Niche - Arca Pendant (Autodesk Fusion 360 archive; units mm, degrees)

design "Arca" references "Arca", "Niche - Chief Architect - Luxe Single Pendant Cordset", "Luxe Single Pendant Cordset - 4ft Standard"
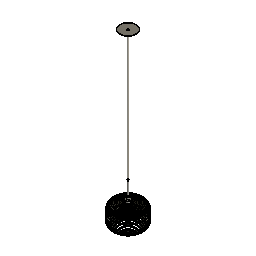
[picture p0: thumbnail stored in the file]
external_derived "ExternalDerived1" bodies "Arca"
external_derived "ExternalDerived2" bodies "Socket Body", "Shade Ring", "Shade Ring +Collar", "Socket", "Body1", "Metal Strain Relief", "Fabric Cord (1)", "Stem (Threaded)"
align "Align1"
external_derived "ExternalDerived3" bodies "G30-Bulb"
align "Align2"
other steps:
derived_base_feature "Derived Base Feature1" bodies "Arca"
derived_base_feature "Derived Base Feature2" bodies "Socket Body", "Shade Ring", "Shade Ring +Collar", "Socket", "Body1", "Metal Strain Relief", "Fabric Cord (1)", "Stem (Threaded)"
derived_base_feature "Derived Base Feature3" bodies "G30-Bulb"
named bodies: "Arca", "Socket Body", "Shade Ring", "Shade Ring +Collar", "Socket", "Body1", "Metal Strain Relief", "Fabric Cord (1)", "Stem (Threaded)", "Cap (Threaded)", "5M Set Screw", "G30-Bulb"

design "Luxe Single Pendant Cordset - 4ft Standard" references "Luxe Canopy - Single Pendant Cordset"
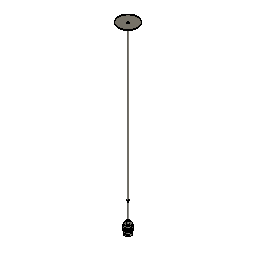
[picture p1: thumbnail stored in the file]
external_derived "ExternalDerived2" bodies "Cap (Threaded)"
move "Move1"
move "Move2"
offset_faces "OffsetFaces1" distance 1051.56
move "Move3"
move "Move4"
move "Move5"
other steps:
derived_base_feature "Derived Base Feature9" bodies "Socket Body", "Shade Ring", "Shade Ring +Collar", "Socket"
derived_base_feature "Derived Base Feature10" bodies "Body1"
derived_base_feature "Derived Base Feature12" bodies "Metal Strain Relief"
derived_base_feature "Derived Base Feature13" bodies "Fabric Cord (1)"
derived_base_feature "Derived Base Feature14" bodies "Stem (Threaded)"
derived_base_feature "Derived Base Feature15" bodies "Cap 9Threaded)", "Cap (Threaded)"
named bodies: "Socket Body", "Shade Ring", "Shade Ring +Collar", "Socket", "Metal Strain Relief", "Fabric Cord (1)", "Stem (Threaded)", "Cap 9Threaded)", "Body1", "Cap (Threaded)", "5M Set Screw"

design "Luxe Canopy - Single Pendant Cordset" references "Luxe Cordset", "Canopy Mounting Bar", "M5 Set Screw", "Canopy Mounting Bar Screw", "Plastic Strain Relief"
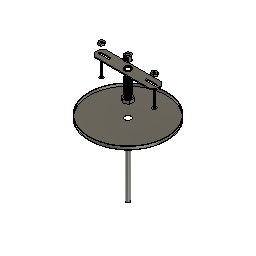
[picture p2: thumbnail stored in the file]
sketch "Sketch1" plane through (0, 0, 0) normal (0, 0, 1) x axis (1, 0, 0)
  circle C1 centre (0, 0) radius 63.5
  point P1 (0, 0)
  point P2 (0, 0)
  coincident P1 P2
  dimension "d1" diameter C1 = 127
extrude "Extrude1" new body sketch "Sketch1" along normal blind 5.08
shell "Shell1" innerThickness 0.762
hole "Hole1" HoleDepth 35.56 HoleDiameter 10.16 TipAngle 118
component_from_bodies "Body->Comp1"
component_insert "Component Insert1"
component_insert "Component Insert2"
component_insert "Component Insert3"
sketch "Sketch2" plane through (0, 0, 0) normal (0, 0, 1) x axis (1, 0, 0)
  circle C1 centre (0, 0) radius 3.175
  point P1 (0, 0)
  point P2 (0, 0)
  coincident P1 P2
  dimension "d8" diameter C1 = 6.35
extrude "Extrude2" new body sketch "Sketch2" along normal blind 127 and against normal blind 127 bodies "Fabric Cord"
component_insert "Component Insert4"
component_insert "Component Insert5"
position "Position1"
sketch "Sketch3" plane through (0, 0, 0.762) normal (0, 0, 1) x axis (-1, 0, 0)
  circle C1 centre (-0.0475, 0.2257) radius 5.08
  circle C2 centre (0, 0) radius 62.738
  circle C3 centre (0, 0) radius 4.826
  concentric C2 C3
  dimension "d13" diameter C3 = 9.652
extrude "Extrude3" new body sketch "Sketch3" profile of C3 along normal blind 25.4 bodies "Threaded Nipple"
shell "Shell2" innerThickness 1.27
thread "Thread1"
sketch "Sketch5" plane through (0, 0, 127) normal (0, 0, 1) x axis (-1, 0, 0)
  line L1 (-6.8191, 3.937) -> (0, 7.874)
  line L2 (-6.8191, -3.937) -> (-6.8191, 3.937)
  line L3 (0, -7.874) -> (-6.8191, -3.937)
  line L4 (6.8191, -3.937) -> (0, -7.874)
  line L5 (6.8191, 3.937) -> (6.8191, -3.937)
  line L6 (0, 7.874) -> (6.8191, 3.937)
  circle C1 centre (0, 0) radius 3.175
  point P2 (0, 0)
  point P9 (0, 0)
  point P3 (0, 7.874)
  coincident P2 P9
  dimension "d20" distance P3 P9 = 7.874
extrude "Extrude4" new body sketch "Sketch5" along normal blind 5.08 bodies "Hex Nut"
move "Move1"
thread "Thread2"
move "Move2" TranslateX 0 TranslateY 0 TranslateZ -55.88
move "Move3" TranslateX 0 TranslateY 0 TranslateZ 60.96
position "Position2"
sketch "Sketch6" plane through (0, 0, 0) normal (0, 0, 1) x axis (1, 0, 0)
  circle C1 centre (0, 0) radius 9.525
  point P1 (0, 0)
  point P2 (0, 0)
  coincident P1 P2
  dimension "d29" diameter C1 = 19.05
extrude "Extrude5" new body sketch "Sketch6" along normal blind 16.129 bodies "Metal Strain Relief"
move "Move4" TranslateX 0 TranslateY 0 TranslateZ -86.36
hole "Hole2" HoleDepth 10.16 HoleDiameter 5.08 TipAngle 118
hole "Hole3" HoleDepth 4.064 HoleDiameter 7.62 TipAngle 180
hole "Hole4" HoleDepth 12.192 HoleDiameter 9.144 TipAngle 180
thread "Thread3" ThreadOffset 0 ThreadLength 6.096
move "Move1" TranslateX 0 TranslateY 0 TranslateZ 68.58
move "Move5" TranslateX 0 TranslateY 0 TranslateZ 138.43
component_insert "Component Insert6"
external_derived "ExternalDerived1" bodies "5M Set Screw"
move "Move6" TranslateX 0 TranslateY 0 TranslateZ -185.42
copy_paste_bodies "CopyPasteBodies1"
move "Move7" TranslateX 0 TranslateY 0 TranslateZ -12.7
offset_faces "OffsetFaces1" distance -152.4
move "Move8"
component_from_bodies "Body->Comp2"
component_from_bodies "Body->Comp3"
component_from_bodies "Body->Comp4"
component_from_bodies "Body->Comp5"
hole "Hole1" HoleDepth 25.4 HoleDiameter 6.35 TipAngle 180
sketch "Sketch7" plane through (0, 0, 0) normal (0, 0, 1) x axis (1, 0, 0)
  line L1 (49.784, 3.9595) -> (52.07, 0)
  line L2 (45.212, 3.9595) -> (49.784, 3.9595)
  line L3 (42.926, 0) -> (45.212, 3.9595)
  line L4 (45.212, -3.9595) -> (42.926, 0)
  line L5 (49.784, -3.9595) -> (45.212, -3.9595)
  line L6 (52.07, 0) -> (49.784, -3.9595)
  point P2 (52.07, 0)
  point P8 (47.498, 0)
  dimension "d63" distance P2 P8 = 4.572
extrude "Extrude6" new body sketch "Sketch7" along normal blind 3.175 bodies "Mounting Hex Nut"
hole "Hole5" HoleDepth 25.4 HoleDiameter 3.81 TipAngle 180
thread "Thread4"
move "Move9"
component_from_bodies "Body->Comp6"
copy_paste "CopyPaste1"
move "Move10"
derived_base_feature "Derived Base Feature3" bodies "Stem (Threaded)", "Cap 9Threaded)"
move "Move11"
component_from_bodies "Body->Comp7"
component_from_bodies "Body->Comp8"
component_from_bodies "Body->Comp9"
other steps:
base_feature "Base Feature1"
base_feature "Base Feature1" bodies "Stem (Threaded)"
base_feature "Base Feature1" bodies "Cap 9Threaded)"
base_feature "Base Feature1" bodies "Fabric Cord"
base_feature "Base Feature1" bodies "Metal Strain Relief"
base_feature "Base Feature1" bodies "Mounting Hex Nut"
base_feature "Base Feature1" bodies "Hex Nut"
base_feature "Base Feature1" bodies "Fabric Cord (1)"
base_feature "Base Feature1" bodies "Threaded Nipple"
derived_base_feature "Derived Base Feature1" bodies "Socket Body", "Shade Ring", "Shade Ring +Collar", "Socket", "Rigid Stem"
derived_base_feature "Derived Base Feature2" bodies "5M Set Screw"
base_feature "Base Feature1" bodies "Fabric Cord", "Fabric Cord (1)"
create_component "CreateComponent1"
remove_body "RemoveBody1"
create_component "CreateComponent2"
remove_body "RemoveBody2"
create_component "CreateComponent3"
remove_body "RemoveBody3"
create_component "CreateComponent4"
remove_body "RemoveBody4"
create_component "CreateComponent5"
remove_body "RemoveBody5"
create_component "CreateComponent6"
remove_body "RemoveBody6"
create_component "CreateComponent7"
remove_body "RemoveBody7"
create_component "CreateComponent8"
remove_body "RemoveBody8"
create_component "CreateComponent9"
remove_body "RemoveBody9"
named bodies: "Fabric Cord", "Threaded Nipple", "Hex Nut", "Metal Strain Relief", "Socket Body", "Shade Ring", "Shade Ring +Collar", "Socket", "Rigid Stem", "5M Set Screw", "Fabric Cord (1)", "Mounting Hex Nut", "Stem (Threaded)", "Cap 9Threaded)"

design "M5 Set Screw"
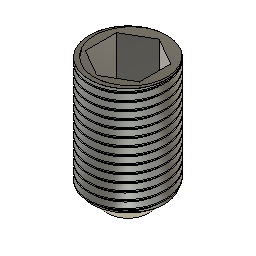
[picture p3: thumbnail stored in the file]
sketch "Sketch1" plane through (0, 0, 0) normal (0, 0, 1) x axis (1, 0, 0)
  circle C1 centre (0, 0) radius 2.5
  point P1 (0, 0)
  point P2 (0, 0)
  coincident P1 P2
  dimension "d1" diameter C1 = 5
extrude "Extrude1" new body sketch "Sketch1" along normal blind 8
sketch "Sketch2" plane through (0, 0, 8) normal (0, 0, 1) x axis (-1, 0, 0)
  line L1 (-1.7321, 1) -> (0, 2)
  line L2 (-1.7321, -1) -> (-1.7321, 1)
  line L3 (0, -2) -> (-1.7321, -1)
  line L4 (1.7321, -1) -> (0, -2)
  line L5 (1.7321, 1) -> (1.7321, -1)
  line L6 (0, 2) -> (1.7321, 1)
  circle C1 centre (0, 0) radius 2.5
  point P2 (0, 0)
  point P9 (0, 0)
  coincident P2 P9
extrude "Extrude2" cut sketch "Sketch2" profile of L1 L2 L3 L4 L5 L6 against normal blind 3
thread "Thread1" ThreadOffset 0.99 ThreadLength 7
chamfer "Chamfer1" distance 1.15

design "Luxe Cordset" references "M5 Set Screw"
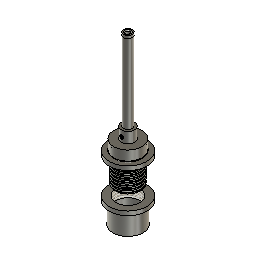
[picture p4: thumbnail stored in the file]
sketch "Sketch1" plane through (0, 0, 0) normal (0, 0, 1) x axis (1, 0, 0)
  circle C1 centre (0, 0) radius 20.6
  point P1 (0, 0)
  point P2 (0, 0)
  coincident P1 P2
  dimension "d11" diameter C1 = 41.2
extrude "Extrude1" new body sketch "Sketch1" along normal blind 14 bodies "Socket Body"
sketch "Sketch2" plane through (0, 0, 14) normal (0, 0, 1) x axis (-1, 0, 0)
  circle C1 centre (0, 0) radius 20.6
  circle C2 centre (0, 0) radius 9.6
  concentric C1 C2
  dimension "d3" diameter C2 = 19.2
extrude "Extrude2" add sketch "Sketch2" profile of C2 along normal blind 15.75
sketch "Sketch3" plane through (0, 0, 29.75) normal (0, 0, 1) x axis (-1, 0, 0)
  circle C1 centre (0, 0) radius 9.6
  circle C2 centre (0, 0) radius 5.75
  concentric C1 C2
  dimension "d6" diameter C2 = 11.5
extrude "Extrude3" new body sketch "Sketch3" profile of C2 along normal blind 114 bodies "Rigid Stem"
move "Move1"
sketch "Sketch4" plane through (0, 0, 203.75) normal (0, 0, 1) x axis (-1, 0, 0)
  circle C1 centre (0, 0) radius 5.75
  circle C2 centre (0, 0) radius 27.5
  dimension "d10" diameter C2 = 55
extrude "Extrude4" new body sketch "Sketch4" profile of C2 along normal blind 6 bodies "Shade Ring"
hole "Hole1" HoleDepth 25 HoleDiameter 42.75 TipAngle 118
sketch "Sketch5" plane through (0, 0, 0) normal (0, 0, 1) x axis (1, 0, 0)
  circle C1 centre (0, 0) radius 22
  point P1 (0, 0)
  point P2 (0, 0)
  coincident P1 P2
  dimension "d18" diameter C1 = 44
move "Move2"
copy_paste_bodies "CopyPasteBodies1"
move "Move3"
sketch "Sketch6" plane through (0, 0, 60) normal (0, 0, -1) x axis (1, 0, 0)
  circle C1 centre (0, 0) radius 20.6
  circle C2 centre (0, 0) radius 21.375
  circle C3 centre (0, 0) radius 20
  concentric C1 C2
  concentric C1 C3
  dimension "d21" diameter C2 = 42.75
  dimension "d24" diameter C3 = 40
cylinder_primitive "CylinderPrimitive1" Height 8 Diameter 42.75
thread "Thread1"
thread "Thread3"
hole "Hole2" HoleDepth 18 HoleDiameter 39 TipAngle 180
move "Move4"
move "Move5"
move "Move6"
hole "Hole3" HoleDepth 114 HoleDiameter 7.6 TipAngle 180
derived_base_feature "Derived Base Feature" bodies "Socket"
move "Move7"
scale "Scale1" ScaleX 1.2 ScaleY 1.2
move "Move8"
sketch "Sketch8" plane through (0, 0, -23.9827) normal (0, 0, -1) x axis (1, 0, 0)
  circle C1 centre (0, -0.036) radius 27.5
  circle C2 centre (0, -0.036) radius 22
  circle C3 centre (0, -0.036) radius 19.5
  dimension "d36" diameter C2 = 44
  dimension "d42" = -2.5
extrude "Extrude7" add sketch "Sketch8" profile of C2 C3 along normal blind 30
offset_faces "OffsetFaces1" distance 2.75
offset_faces "OffsetFaces2" distance -9
thread "Thread2"
move "Move9"
move "Move10"
move "Move11"
scale "Scale2" ScaleZ 1.2
move "Move12"
move "Move13"
move "Move14"
move "Move15"
move "Move16"
split_face "SplitFace1"
move "Move17"
move "Move18"
move "Move19"
move "Move20"
move "Move21"
move "Move22"
move "Move23"
move "Move24"
move "Move25"
move "Move26"
move "Move27"
thread "Thread4"
move "Move28"
move "Move29"
move "Move30"
hole "Hole4" HoleDepth 21 HoleDiameter 39.35 TipAngle 180
hole "Hole5" HoleDepth 9 HoleDiameter 5 TipAngle 180
move "Move31"
move "Move32"
hole "Hole6" HoleDepth 20 HoleDiameter 10 TipAngle 180
move_face "MoveFace3"
move "Move33"
move "Move34"
move "Move35"
move "Move36"
move "Move37"
thread "Thread5" ThreadOffset 0 ThreadLength 6
thread "Thread6" ThreadOffset 0 ThreadLength 6
move "Move38"
move "Move39"
move "Move40"
move "Move41"
component_insert "Component Insert"
thread "Thread7" ThreadOffset 0.5 ThreadLength 5.337
chamfer "Chamfer1" distance 0.5 distance 0.35
sketch "Sketch12" plane through (0, 0, 0) normal (0, 0, 1) x axis (1, 0, 0)
  circle C1 centre (0, 0) radius 6.35
  dimension "d60" diameter C1 = 12.7
extrude "Extrude8" new body sketch "Sketch12" along normal blind 115 bodies "Stem (Threaded)"
hole "Hole7" HoleDepth 115 HoleDiameter 9.65 TipAngle 118
thread "Thread8" ThreadOffset 0 ThreadLength 12.5
thread "Thread9" ThreadOffset 0 ThreadLength 12.5
sketch "Sketch13" plane through (0, 0, 0) normal (0, 0, 1) x axis (1, 0, 0)
  circle C1 centre (0, 0) radius 6.35
  point P1 (0, 0)
  point P2 (0, 0)
  coincident P1 P2
  dimension "d70" diameter C1 = 12.7
extrude "Extrude9" new body sketch "Sketch13" along normal blind 4 bodies "Cap 9Threaded)"
sketch "Sketch14" plane through (0, 0, 4) normal (0, 0, 1) x axis (-1, 0, 0)
  circle C1 centre (0, 0) radius 6.35
  circle C2 centre (0, 0) radius 4.5
  concentric C1 C2
  dimension "d73" diameter C2 = 9
extrude "Extrude10" add sketch "Sketch14" profile of C2 against normal blind 14
thread "Thread10"
hole "Hole8" HoleDepth 115 HoleDiameter 6.5 TipAngle 118 CSDiameter 9 CSAngle 90
move "Move42"
move "Move43"
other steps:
base_feature "Base Feature" bodies "Shade Ring +Collar"
named bodies: "Socket Body", "Shade Ring", "Shade Ring +Collar", "Socket", "Rigid Stem", "Stem (Threaded)", "Cap 9Threaded)"

design "Niche - Chief Architect - Luxe Single Pendant Cordset"
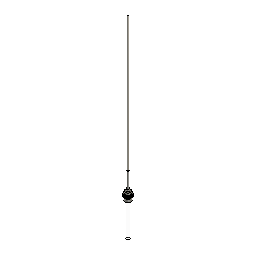
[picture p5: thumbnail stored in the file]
derived_base_feature "Derived Base Feature" bodies "Socket Body", "Shade Ring", "Shade Ring +Collar", "Socket", "Canopy", "Metal Strain Relief", "Fabric Cord (1)", "Stem (Threaded)"
remove_body "RemoveBody1"
remove_body "RemoveBody2"
split "Split1" bodies "Socket Body (1)"
remove_body "RemoveBody3"
align "Align1"
hole "Hole1" HoleDepth 19.05 HoleDiameter 8.89 TipAngle 118
combine "Combine1" bodies "Shade Ring"
split "Split2" bodies "Socket (1)"
remove_body "RemoveBody4"
split "Split3" bodies "Fabric Cord (1) (1)"
remove_body "RemoveBody5"
combine "Combine2" bodies "Socket Body"
align "Align2"
combine "Combine3" bodies "Metal Strain Relief"
sketch "Sketch1" plane through (0, 0, 0) normal (0, 1, 0) x axis (1, 0, 0)
  line L1 (13.1098, 24.9049) -> (-12.2902, 24.9049)
  line L2 (18.1898, 37.1766) -> (18.1898, 29.9849)
  line L3 (-17.3702, 29.9849) -> (-17.3702, 36.7132)
  line L4 (0, 132.969) -> (0, 24.9049)
  arc A1 centre (0, 86.36) radius 46.609 clockwise from (-22.6031, 45.5985) to (23.276, 45.979)
  arc A2 centre (-27.5302, 36.7132) radius 10.16 clockwise from (-22.6031, 45.5985) to (-17.3702, 36.7132)
  arc A3 centre (28.3498, 37.1766) radius 10.16 clockwise from (18.1898, 37.1766) to (23.276, 45.979)
  arc A4 centre (-12.2902, 29.9849) radius 5.08 clockwise from (-12.2902, 24.9049) to (-17.3702, 29.9849)
  arc A5 centre (13.1098, 29.9849) radius 5.08 clockwise from (18.1898, 29.9849) to (13.1098, 24.9049)
  point P5 (18.1898, 43.4469)
  point P3 (-17.3702, 24.9049)
  point P4 (18.1898, 24.9049)
  point P18 (0, 24.9049)
  point P19 (0, 132.969)
  horizontal L1
  vertical L2
  vertical L3
  tangent A1 A2
  tangent L3 A2
  coincident P5 L2
  coincident P5 A1
  tangent L2 A3
  tangent A1 A3
  equal A2 A3
  coincident P3 L1
  coincident P3 L3
  tangent L1 A4
  tangent L3 A4
  coincident P4 L1
  coincident P4 L2
  tangent L1 A5
  tangent L2 A5
  coincident L1 P18
  coincident A1 P19
  perpendicular L1 L4
  dimension "d4" diameter A1 = 93.218
  dimension "d5" distance P3 P4 = 35.56
  dimension "d6" distance P4 P5 = 18.542
  dimension "d7" radius A2 = 10.16
  dimension "d8" radius A4 = 5.08
  dimension "d9" radius A5 = 5.08
revolve "Revolve1" sketch "Sketch1" AlongAngle 360 bodies "G30-Bulb"
move "Move1"
sketch "Sketch2" plane through (0, 0, 0) normal (0, 1, 0) x axis (1, 0, 0)
  line L1 (12.7, 0) -> (-12.7, 0)
  line L2 (12.7, 152.4) -> (12.7, 0)
  line L3 (-12.7, 0) -> (-12.7, 152.4)
  line L4 (0, 165.1) -> (0, 0)
  arc A1 centre (0, 152.4) radius 12.7 clockwise from (-12.7, 152.4) to (12.7, 152.4)
  point P1 (0, 0)
  point P7 (0, 0)
  point P8 (0, 165.1)
  horizontal L1
  vertical L2
  vertical L3
  coincident P1 P7
  midpoint A1 P8
  perpendicular L1 L4
revolve "Revolve2" sketch "Sketch2" AlongAngle 360 bodies "T9-Bulb"
move "Move2"
sketch "Sketch3" plane through (0, 0, 0) normal (0, 1, 0) x axis (1, 0, 0)
  line L1 (12.7, 0) -> (-12.7, 0)
  line L2 (12.7, 254) -> (12.7, 0)
  line L3 (-12.7, 0) -> (-12.7, 254)
  line L4 (0, 266.7) -> (0, 0)
  arc A1 centre (0, 254) radius 12.7 clockwise from (-12.7, 254) to (12.7, 254)
  point P1 (0, 0)
  point P7 (0, 0)
  point P8 (0, 266.7)
  horizontal L1
  vertical L2
  vertical L3
  coincident P1 P7
  midpoint A1 P8
  perpendicular L1 L4
revolve "Revolve3" sketch "Sketch3" AlongAngle 360 bodies "T8-Bulb"
move "Move3"
move "Move4"
move "Move5"
sketch "Sketch4" plane through (0, 0, 0) normal (0, 1, 0) x axis (1, 0, 0)
  line L1 (15.875, -8.763) -> (-15.875, -8.763)
  line L2 (15.875, 22.987) -> (15.875, -8.763)
  line L3 (-15.875, 22.987) -> (15.875, 22.987)
  line L4 (-15.875, -8.763) -> (-15.875, 22.987)
  line L5 (0, 22.987) -> (0, -8.763)
  point P6 (0, -8.763)
  point P7 (0, 22.987)
  point P2 (-15.875, -8.763)
  point P3 (15.875, -8.763)
  point P5 (-15.875, 22.987)
  horizontal L1
  vertical L2
  horizontal L3
  vertical L4
  midpoint L1 P6
  midpoint L3 P7
  dimension "d13" distance P2 P3 = 31.75
  dimension "d14" distance P2 P5 = 31.75
revolve "Revolve4" sketch "Sketch4" AlongAngle 360 bodies "Bulb Extender"
move "Move6"
sketch "Sketch5" plane through (0, 0, 0) normal (0, 1, 0) x axis (1, 0, 0)
  line L1 (-12.7, 35.56) -> (12.7, 35.56)
  line L2 (-12.7, 5.08) -> (-12.7, 35.56)
  line L3 (12.7, 5.08) -> (-12.7, 5.08)
  line L4 (12.7, 35.56) -> (12.7, 5.08)
  line L5 (-12.7, 5.08) -> (12.7, 35.56)
  line L6 (12.7, 5.08) -> (-12.7, 35.56)
  line L7 (0, 35.56) -> (0, 5.08)
  point P6 (0, 20.32)
  point P7 (0, 5.08)
  point P8 (0, 35.56)
  horizontal L1
  perpendicular L1 L2
  parallel L1 L3
  parallel L2 L4
  coincident L5 P6
  coincident L6 P6
  midpoint L3 P7
  midpoint L1 P8
revolve "Revolve5" sketch "Sketch5" AlongAngle 360 bodies "Y-Spliter"
sketch "Sketch6" plane through (0, 0, 0) normal (0, 1, 0) x axis (1, 0, 0)
  line L1 (-55.88, 64.9514) -> (-21.59, 64.9514)
  line L2 (-55.88, 35.7414) -> (-55.88, 64.9514)
  line L3 (-21.59, 35.7414) -> (-55.88, 35.7414)
  line L4 (-21.59, 64.9514) -> (-21.59, 35.7414)
  line L5 (-55.88, 35.7414) -> (-21.59, 64.9514)
  line L6 (-21.59, 35.7414) -> (-55.88, 64.9514)
  line L7 (-38.735, 64.9514) -> (-38.735, 35.7414)
  point P6 (-38.735, 50.3464)
  point P7 (-38.735, 35.7414)
  point P8 (-38.735, 64.9514)
  point P4 (-55.88, 35.7414)
  point P5 (-21.59, 35.7414)
  point P2 (-21.59, 64.9514)
  horizontal L1
  perpendicular L1 L2
  parallel L1 L3
  parallel L2 L4
  coincident L5 P6
  coincident L6 P6
  midpoint L3 P7
  midpoint L1 P8
  dimension "d17" distance P4 P5 = 34.29
  dimension "d18" distance P2 P5 = 29.21
revolve "Revolve6" sketch "Sketch6" AlongAngle 360
chamfer "Chamfer1" distance 7.62
move "Move7"
mirror "Mirror1" mirrorStitchTolerance 0.1016
move "Move8"
combine "Combine4"
move "Move9"
sketch "Sketch7" plane through (0, 0, 0) normal (0, 1, 0) x axis (1, 0, 0)
  line L1 (-15.24, 40.64) -> (-15.24, 48.1816)
  line L2 (12.7, 38.1) -> (-12.7, 38.1)
  line L3 (15.24, 48.1816) -> (15.24, 40.64)
  line L4 (0, 100.1623) -> (0, 38.1)
  arc A1 centre (0, 76.2) radius 23.9623 clockwise from (-19.7282, 62.5988) to (19.7282, 62.5988)
  arc A2 centre (-40.64, 48.1816) radius 25.4 clockwise from (-19.7282, 62.5988) to (-15.24, 48.1816)
  arc A3 centre (40.64, 48.1816) radius 25.4 clockwise from (15.24, 48.1816) to (19.7282, 62.5988)
  arc A4 centre (-12.7, 40.64) radius 2.54 clockwise from (-12.7, 38.1) to (-15.24, 40.64)
  arc A5 centre (12.7, 40.64) radius 2.54 clockwise from (15.24, 40.64) to (12.7, 38.1)
  point P15 (0, 38.1)
  point P16 (0, 100.1623)
  parallel L1 L3
  tangent A1 A2
  tangent L1 A2
  tangent A1 A3
  tangent L3 A3
  tangent L1 A4
  tangent L2 A4
  tangent L2 A5
  tangent L3 A5
  midpoint L2 P15
  midpoint A1 P16
  perpendicular L2 L4
  dimension "d23" radius A2 = 25.4
  dimension "d24" radius A3 = 25.4
  dimension "d25" radius A4 = 2.54
  dimension "d26" radius A5 = 2.54
revolve "Revolve7" sketch "Sketch7" AlongAngle 360 bodies "A15-Bulb"
move "Move10"
copy_paste_bodies "CopyPasteBodies1"
copy_paste_bodies "CopyPasteBodies2"
move "Move11"
mirror "Mirror2" mirrorStitchTolerance 0.1016 bodies "A15-Bulb (1) (1)"
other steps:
base_feature "Base Feature1" bodies "Y-Spliter", "Bulb Extender", "Y-Spliter (1)", "Bulb Extender (1)"
base_feature "Base Feature2" bodies "A15-Bulb", "A15-Bulb (1)"
named bodies: "Socket Body", "Shade Ring", "Shade Ring +Collar", "Socket", "Canopy", "Metal Strain Relief", "Fabric Cord (1)", "Stem (Threaded)", "Adapter", "5M Set Screw", "Body1 (1)", "Socket Body (1)", "Socket (1)", "Fabric Cord (1) (1)", "G30-Bulb", "T9-Bulb", "T8-Bulb", "Bulb Extender", "Y-Spliter", "A15-Bulb", "Y-Spliter (1)", "Bulb Extender (1)", "A15-Bulb (1)", "A15-Bulb (1) (1)"

design "Plastic Strain Relief"
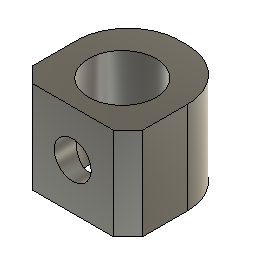
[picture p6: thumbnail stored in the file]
base_feature "Base Feature" bodies "strainrelief"
named bodies: "strainrelief"

design "Arca"
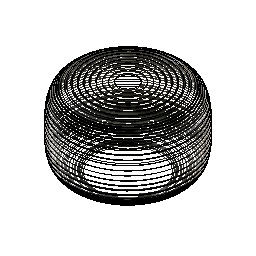
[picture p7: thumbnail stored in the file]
derived_base_feature "Derived Base Feature" bodies "Occulo"
move "Move1"
work_plane "WorkPlane1" AlongDistance -168.275
split "Split1" bodies "Arca"
remove_body "RemoveBody1"
named bodies: "Occulo", "Arca"

design "Canopy Mounting Bar Screw"
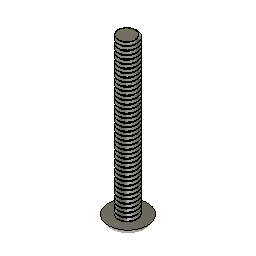
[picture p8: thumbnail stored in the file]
base_feature "Base Feature" bodies "screw1"
named bodies: "screw1"

design "Canopy Mounting Bar"
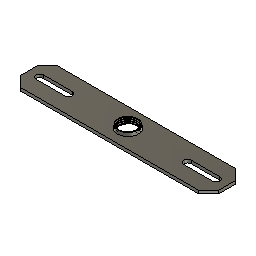
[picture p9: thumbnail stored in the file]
base_feature "Base Feature" bodies "mountingbar"
named bodies: "mountingbar"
